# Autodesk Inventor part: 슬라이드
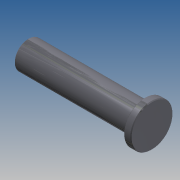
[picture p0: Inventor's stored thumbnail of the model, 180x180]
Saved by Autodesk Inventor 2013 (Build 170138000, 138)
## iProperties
Created: 2013-06
Part Number: 슬라이드
Document SubType Name: Modeling
Designer: SeoGD™[esajin.kr]
Density: 7.86 g/cm^3
Material: 강철, 연강
Mass: 1603.27 g
Surface Area: 269.019 cm^2
Volume: 203.978 cm^3
Author: SeoGD™[esajin.kr]
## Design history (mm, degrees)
sketch "스케치1"
  geometry: L1 (-75, 162)-(-75, 58) reference; L2 (-148, 110)-(22, 110); L3 (-148, 110)-(-148, 129); L4 (-148, 129)-(12, 129); L5 (12, 129)-(12, 139); L6 (12, 139)-(22, 139); L7 (22, 139)-(22, 110); 2 further points
  constraints: 12 end point, 3 parallel, 3 perpendicular, 1 midpoint, 1 point on line
  dimensions: "d0" = 58 diameter of L6 L2; "d1" = 38 diameter of L4 L2; "d2" = 10 distance of L5.end L6.end; "d3" = 170 distance of L2.start L2.end; "d4" = 73 distance between parallel lines of L3 L1
revolve "회전1" sketch "스케치1" stored, may be unused: angle "d5" = 90 deg
hole "구멍1" diameter "d11" = 13.376; stored, may be unused: countersink angle "d15" = 90 deg, drill point angle "d17" = 118 deg; dims "d9" = 10, "d10" = 10, "d12" = 22, "d13" = 4, "d14" = 2, "d16" = 25
chamfer "모따기1" distance "d6" = 1; stored, may be unused: second distance "d7" = 2, angle "d8" = 45 deg
node "솔리드1"
node "참조1"
